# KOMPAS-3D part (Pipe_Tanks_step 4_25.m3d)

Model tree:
1. X Axis
2. Y Axis
3. Z Axis  (labels: Bend 90 Dn 20; Pipe Dn 20)
     Òîëùèíà ñòåíêè 1 = 1

Referenced files in C:\Documents and Settings\kashirsky\Мои документы\Camtasia Studio\Pipelines3D\Tanks\: Tanks_step 4.a3d
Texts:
  Pipe Dn 20
  Steel ASTM A295
  Three Point Plane
  Plane at Angle
  Line and Point Plane
  Axis through Two Vertices
  Axis of Feature
  Axis of Conical Surface
  Axis through Edge
  Trim by Surface
  Trim by Sketch
  Feature with No History
  Intersection Axis of Two Planes
  Two Line Plane
  Line and Face Plane
  Bend by line
  Hole in sheet body
  Cut in sheet body
  Point in CM
  Linear Dimension from Line to Point
  Surface Finish Symbol
  Geometric Tolerance Symbol
  Leader #1
  Leader #2
  Leader #3
  Shape Deviations and Datum
  Node point number
  Mark of coordination axis
  Node point designation
  Mark/Reference designation with leader
  Mark/reference designation on line
  Mark/Reference designation without leader
  Bend 90 Dn 20
  Plane of section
